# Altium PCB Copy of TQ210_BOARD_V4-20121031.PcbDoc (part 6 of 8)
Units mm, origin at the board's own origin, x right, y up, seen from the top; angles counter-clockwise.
Board outline 191.2 x 131.27 mm, 2 copper layers (TopLayer, BottomLayer); 362 components, 455 nets, 1594 pads, 630 vias.
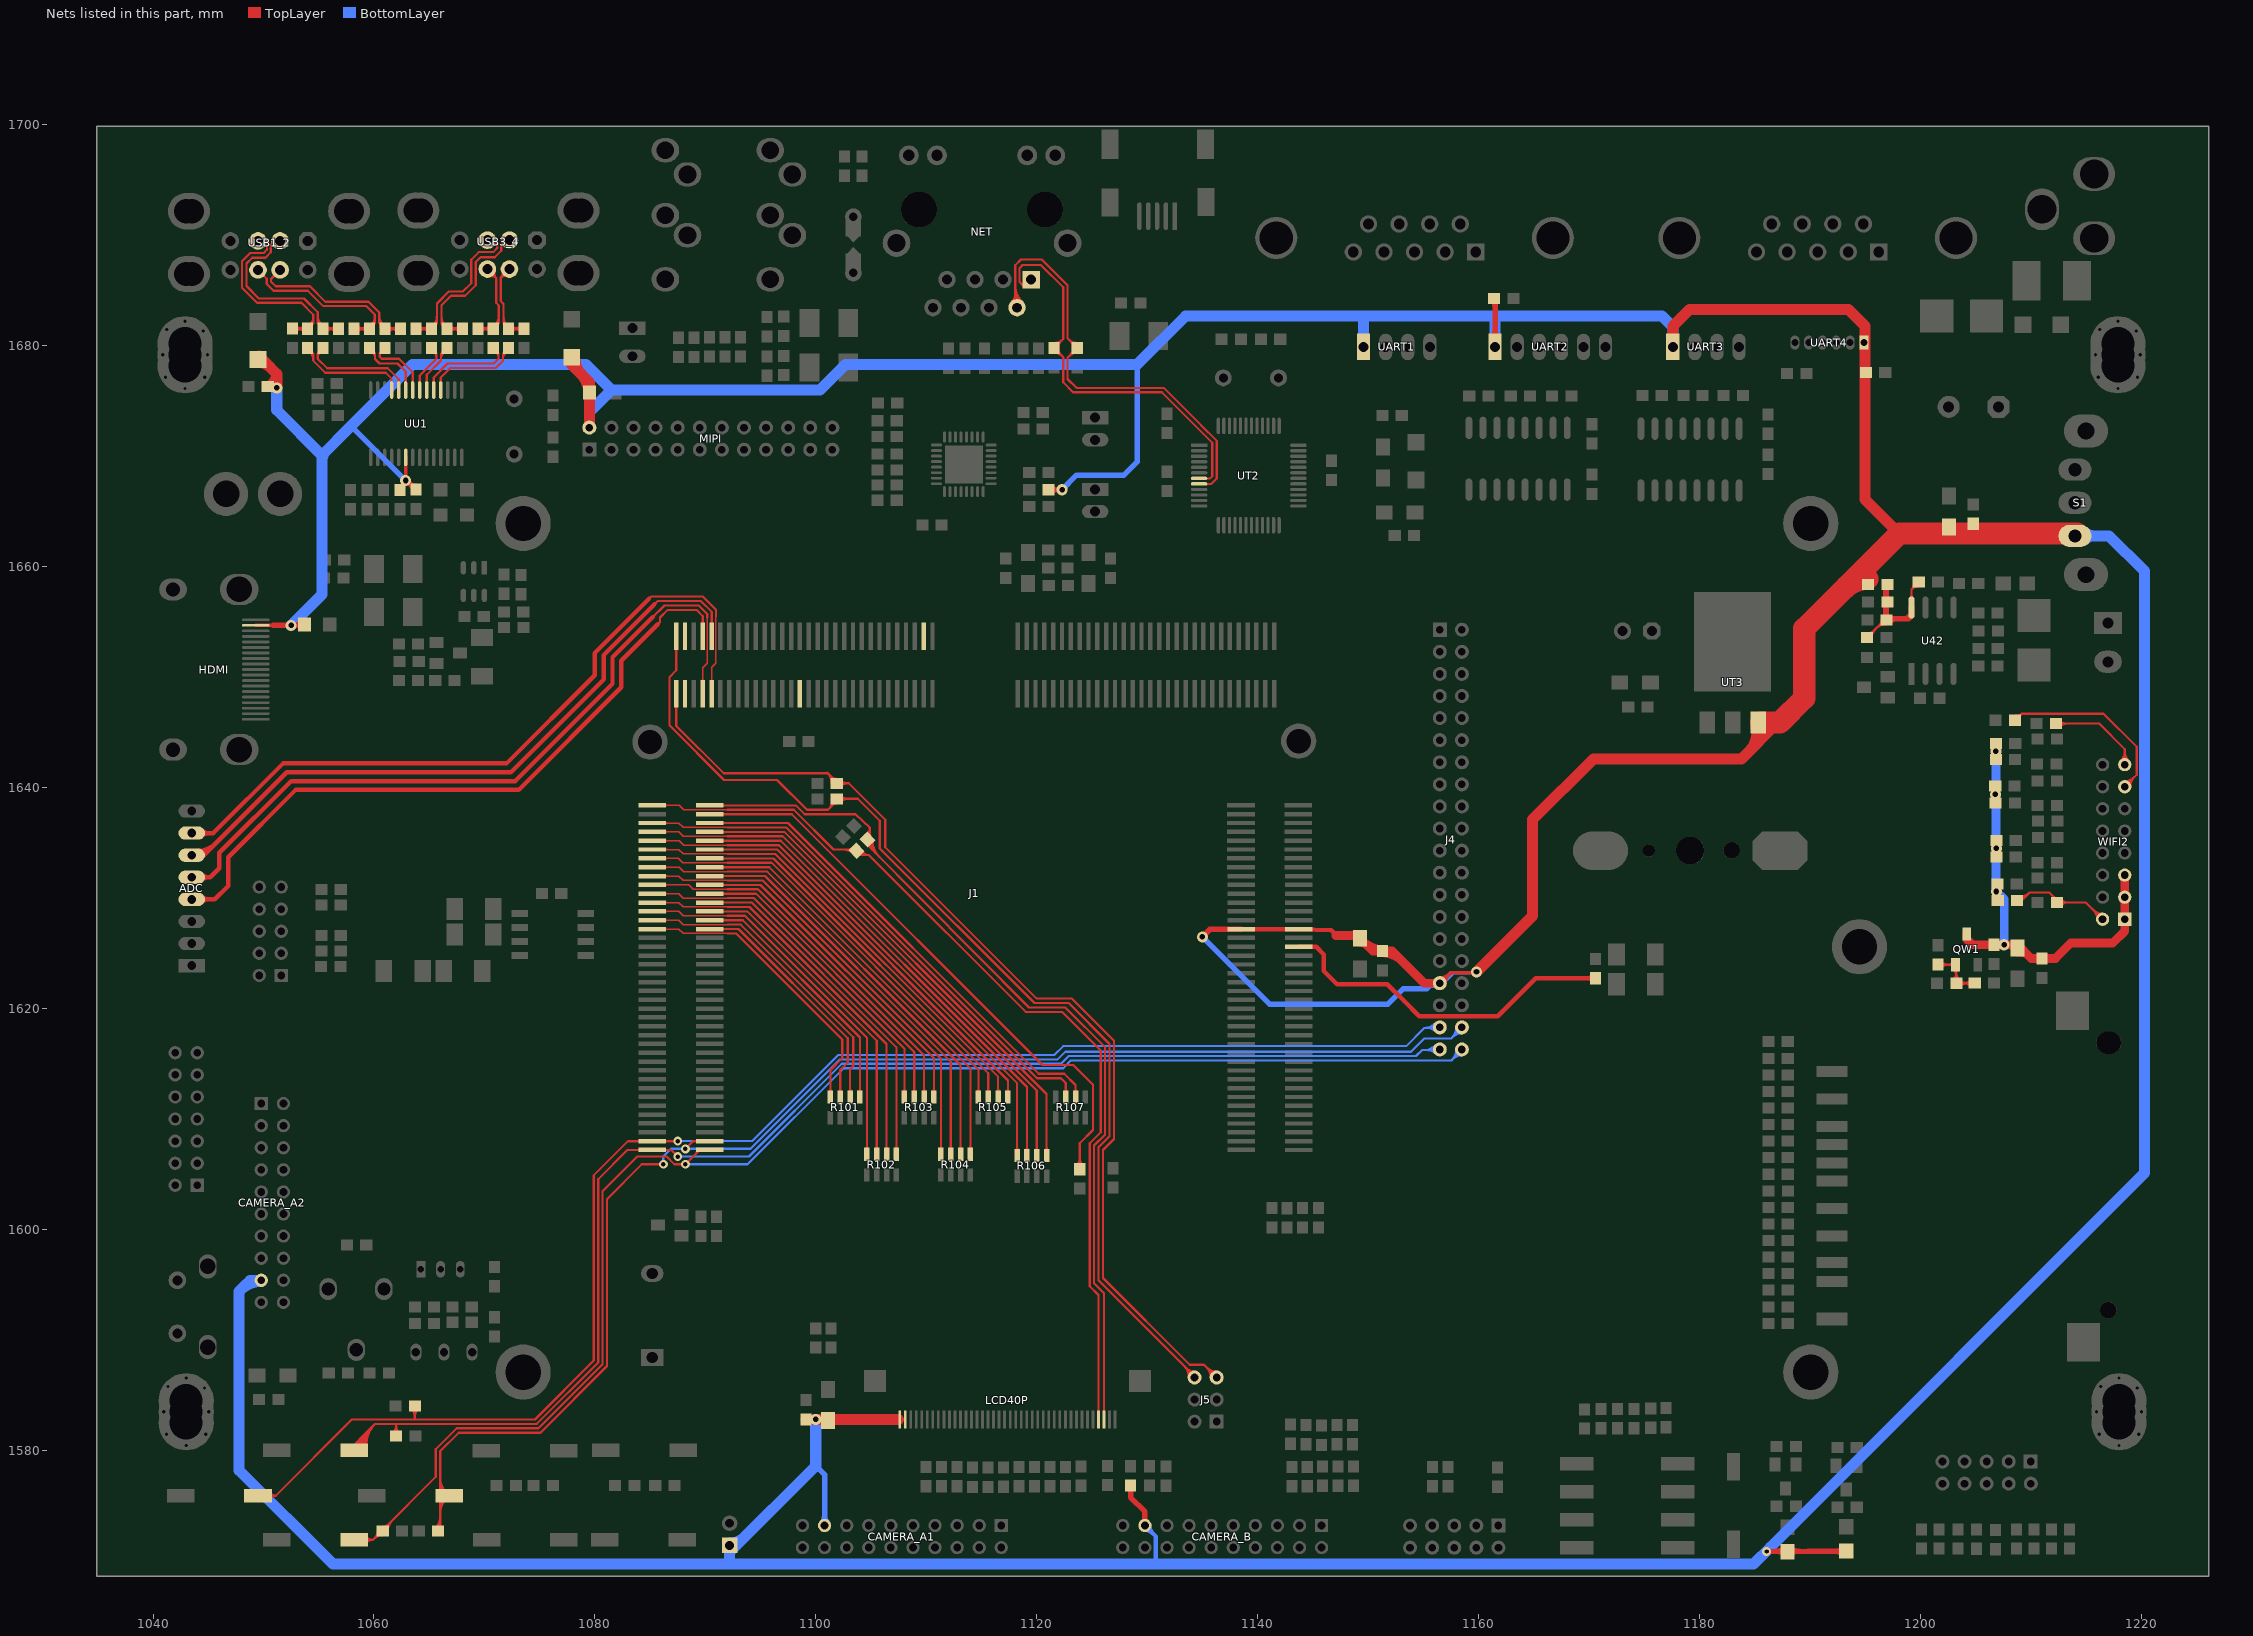
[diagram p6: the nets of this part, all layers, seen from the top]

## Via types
v1: diameter 1, hole 0.5, TopLayer to BottomLayer, 458 vias
v2: diameter 0.8, hole 0.4, TopLayer to BottomLayer, 172 vias

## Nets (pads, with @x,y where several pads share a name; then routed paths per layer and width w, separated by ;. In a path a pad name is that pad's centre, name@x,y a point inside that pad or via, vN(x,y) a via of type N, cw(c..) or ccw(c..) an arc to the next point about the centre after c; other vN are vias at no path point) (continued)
SD3_WPN: RW8.2 RW16.2 WIFI2.2 | length 17.4
  TopLayer w0.2: RW8.2@1208.765,1629.774 1209.174,1629.774 1209.9,1630.5 ; RW8.2@1208.815,1629.774 ccw(c1208.912,1630.38) 1209.346,1629.946 ; RW8.2@1208.846,1629.971 ccw(c1208.988,1630.858) 1209.623,1630.223 ; RW8.2@1208.878,1630.169 ccw(c1209.065,1631.335) 1209.9,1630.5 ; 1211.866,1630.339 cw(c1211.236,1629.71) RW16.2@1212.122,1629.624 ; RW16.2@1212.114,1630.091 ccw(c1212.321,1630.298) RW16.2@1212.321,1630.005 ; RW16.2@1212.371,1629.605 1214.995,1629.605 WIFI2.2@1216.512,1628.088 ; RW16.2@1212.6,1629.605 1211.705,1630.5 1209.9,1630.5 ; RW16.2@1212.704,1629.322 cw(c1213.387,1628.639) 1213.387,1629.605 cw(c1213.387,1630.571) RW16.2@1212.704,1629.888 ; WIFI2.2@1216.012,1628.088 ccw(c1214.805,1628.088) 1215.658,1628.942 ccw(c1216.512,1629.795) WIFI2.2@1216.512,1628.588 ; WIFI2.2@1216.212,1628.088 ccw(c1215.487,1628.088) 1215.999,1628.6 ccw(c1216.512,1629.112) WIFI2.2@1216.512,1628.388
SYS_OE: J1.84
TSXM0: ADC.6 J1.89 | length 63.1
  TopLayer w0.2: 1085.4,1656.6 1085.7,1656.9 1089.595,1656.9 1090.575,1655.92 J1.89@1090.575,1653.687
  TopLayer w0.4: ADC.6@1043.502,1633.888 1044.588,1633.888 1052.1,1641.4 1072.4,1641.4 1080.804,1649.804 1080.804,1652.004 1085.4,1656.6 ; ADC.6@1044.102,1633.888 ccw(c1044.102,1635.061) 1044.931,1634.231 ; ADC.6@1044.102,1634.288 ccw(c1044.102,1636.427) 1045.614,1634.914
TSXM1: CL1.1 J1.79 LCD40P.37 | length 89.3
  TopLayer w0.135: J1.79@1085.2,1638.4 1087.658,1638.4 1088.058,1638 1092,1638 ; J1.79@1086.344,1638.306 cw(c1086.57,1638.08) 1086.57,1638.4 cw(c1086.57,1638.72) J1.79@1086.344,1638.494
  TopLayer w0.2: 1092,1638 1098,1638 1101.603,1634.397 1103.603,1634.397 1104.1,1633.9 1104.8,1633.9 ; 1102.536,1634.397 cw(c1102.536,1633.21) CL1.1@1103.375,1634.049 ; 1102.848,1634.397 ccw(c1102.848,1635.142) CL1.1@1103.375,1634.615 ; CL1.1@1103.019,1634.397 cw(c1103.019,1633.693) CL1.1@1103.516,1634.191 ; CL1.1@1103.728,1634.261 ccw(c1104.237,1634.439) 1104.237,1633.9 ; CL1.1@1103.917,1634.327 ccw(c1104.518,1634.537) 1104.518,1633.9 ; CL1.1@1103.931,1633.917 cw(c1104.004,1633.794) 1104.105,1633.895 cw(c1104.21,1634) CL1.1@1104.08,1634.071 ; CL1.1@1104.106,1634.393 ccw(c1104.8,1634.635) 1104.8,1633.9 ; LCD40P.37@1125.6,1582.8 1125.6,1594.064 1124.8,1594.864 1124.8,1607.8 1125.8,1608.8 1125.8,1616.2 1122.3,1619.7 1119,1619.7 1104.8,1633.9
TSXP0: ADC.7 J1.90 | length 67.3
  TopLayer w0.135: J1.90@1090.565,1648.497 1090.565,1650.889 1090.965,1651.289 1090.965,1655.486
  TopLayer w0.2: 1084.9,1657.1 1085.1,1657.3 1089.795,1657.3 1090.955,1656.139 1090.955,1655.496
  TopLayer w0.4: ADC.7@1043.502,1635.888 1045.456,1635.888 1051.769,1642.2 1072,1642.2 1079.986,1650.186 1079.986,1652.186 1084.9,1657.1 ; ADC.7@1044.385,1635.605 cw(c1045.067,1634.922) 1045.067,1635.888 cw(c1045.067,1636.853) ADC.7@1044.385,1636.171
TSXP1: CL2.1 J1.80 LCD40P.38 | length 86.4
  TopLayer w0.2: J1.80@1090.409,1638.385 1090.424,1638.4 1098.2,1638.4 1099,1637.6 1103.6,1637.6 1104.9,1636.4 ; CL2.1@1104.47,1635.686 ccw(c1104.091,1636.4) 1104.9,1636.4 ; CL2.1@1104.564,1635.509 ccw(c1104.268,1636.068) 1104.9,1636.068 ; CL2.1@1104.658,1634.868 cw(c1104.606,1634.578) 1104.9,1634.578 ; CL2.1@1104.728,1635.261 ccw(c1105.903,1635.257) 1105.069,1634.429 ; 1104.9,1634.711 cw(c1105.279,1634.711) CL2.1@1105.011,1634.979 ; CL2.1@1104.928,1635.261 ccw(c1106.586,1635.255) 1105.41,1634.087 ; CL2.1@1105.128,1635.26 ccw(c1107.269,1635.253) 1105.75,1633.744 ; LCD40P.38@1126.1,1583 1126.1,1594.232 1125.2,1595.132 1125.2,1607.6 1126.2,1608.6 1126.2,1616.5 1122.6,1620.1 1119.3,1620.1 1104.9,1634.6 1104.9,1636.4
TSYM0: ADC.4 J1.87 | length 63.9
  TopLayer w0.2: 1085.7,1654.8 1085.9,1655 1085.9,1655.4 1086.6,1656.1 1089.195,1656.1 1089.775,1655.52 J1.87@1089.775,1653.687
  TopLayer w0.4: ADC.4@1043.502,1629.888 1045.588,1629.888 1046.8,1631.1 1046.8,1633.7 1052.9,1639.8 1073.1,1639.8 1082.4,1649.1 1082.4,1651.5 1085.7,1654.8 ; ADC.4@1044.385,1629.605 cw(c1045.067,1628.922) 1045.067,1629.888 cw(c1045.067,1630.853) ADC.4@1044.385,1630.171
TSYM1: CL3.1 J1.81 J5.6 | length 107.3
  TopLayer w0.2: J1.81@1087.294,1652.576 cw(c1087.098,1652.38) 1087.375,1652.38 ; 1087.375,1652.431 cw(c1087.581,1652.431) J1.81@1087.435,1652.576 ; J1.81@1087.375,1653.687 1087.375,1650.625 1086.75,1650 1086.75,1645.65 1091.7,1640.7 1096.5,1640.7 1099.2,1638 1101.1,1638 1102.1,1639 1103.8,1639 1105.8,1637 1105.8,1634.5 1119.8,1620.5 1122.9,1620.5 1126.6,1616.8 1126.6,1608.434 1125.6,1607.434 1125.6,1595.4 1134.3,1586.7 J5.6@1134.3,1586.6 ; 1101.223,1638.123 ccw(c1100.615,1638.731) CL3.1@1101.456,1638.91 ; 1101.483,1638.383 ccw(c1101.044,1638.822) CL3.1@1101.652,1638.951 ; 1101.583,1638.483 cw(c1101.847,1638.219) CL3.1@1101.847,1638.593 ; CL3.1@1102.089,1638.851 cw(c1102.448,1638.492) 1102.448,1639 ; CL3.1@1102.23,1638.71 cw(c1102.931,1638.009) 1102.931,1639 ; CL3.1@1102.23,1639.275 ccw(c1102.895,1639.94) 1102.895,1639 ; 1133.316,1587.684 cw(c1132.232,1586.6) 1133.765,1586.6 ccw(c1132.232,1586.6) 1133.316,1587.684 ; 1133.557,1587.443 ccw(c1134.3,1588.185) 1134.3,1587.135 cw(c1134.3,1588.185) 1133.557,1587.443 ; 1133.657,1587.343 cw(c1132.915,1586.6) 1133.965,1586.6 ccw(c1132.915,1586.6) 1133.657,1587.343 ; 1133.899,1587.101 ccw(c1134.3,1587.502) 1134.3,1586.935 cw(c1134.3,1587.502) 1133.899,1587.101
TSYP0: ADC.5 J1.88 | length 68.8
  TopLayer w0.135: J1.88@1089.671,1649.641 ccw(c1089.445,1649.867) 1089.765,1649.867 ccw(c1090.084,1649.867) J1.88@1089.858,1649.641 ; J1.88@1089.765,1648.497 1089.765,1650.876 1090.164,1651.276 1090.164,1655.391
  TopLayer w0.2: 1085.253,1655.453 1086.3,1656.5 1089.395,1656.5 1090.172,1655.722 1090.172,1655.399
  TopLayer w0.4: ADC.5@1043.502,1631.888 1045.188,1631.888 1046,1632.7 1046,1634.1 1052.5,1640.6 1072.8,1640.6 1081.6,1649.4 1081.6,1651.8 1085.253,1655.453 ; ADC.5@1044.385,1631.605 cw(c1045.067,1630.922) 1045.067,1631.888 cw(c1045.067,1632.853) ADC.5@1044.385,1632.171
TSYP1: CL4.1 J1.82 J5.5 | length 102.8
  TopLayer w0.2: J1.82@1087.294,1647.376 cw(c1087.098,1647.181) 1087.375,1647.181 ; 1087.375,1647.231 cw(c1087.581,1647.231) J1.82@1087.435,1647.376 ; J1.82@1087.375,1648.487 1087.375,1645.591 1091.666,1641.3 1101.1,1641.3 1102,1640.4 1103,1640.4 1106.3,1637.1 1106.3,1634.6 1120,1620.9 1123.2,1620.9 1127,1617.1 1127,1608.2 1126,1607.2 1126,1595.6 1133.852,1587.748 1135.152,1587.748 J5.5@1136.3,1586.6 ; 1101.051,1641.349 cw(c1100.095,1640.393) CL4.1@1101.447,1640.393 ; 1101.393,1641.007 cw(c1100.778,1640.393) CL4.1@1101.647,1640.393 ; 1101.438,1640.962 ccw(c1101.847,1641.372) CL4.1@1101.847,1640.793 ; CL4.1@1102.089,1640.251 cw(c1102.448,1639.892) 1102.448,1640.4 ; CL4.1@1102.23,1640.11 cw(c1102.931,1639.409) 1102.931,1640.4 ; CL4.1@1102.23,1640.675 ccw(c1102.895,1641.34) 1102.895,1640.4 ; 1135.387,1587.513 cw(c1134.473,1586.6) 1135.765,1586.6 ccw(c1134.473,1586.6) 1135.387,1587.513 ; 1135.387,1587.513 ccw(c1136.3,1588.427) 1136.3,1587.135 cw(c1136.3,1588.427) 1135.387,1587.513 ; 1135.728,1587.172 cw(c1135.156,1586.6) 1135.965,1586.6 ccw(c1135.156,1586.6) 1135.728,1587.172 ; 1135.728,1587.172 ccw(c1136.3,1587.744) 1136.3,1586.935 cw(c1136.3,1587.744) 1135.728,1587.172
TX+: NET.1 R206.1 UT2.7 | length 40.3
  TopLayer w0.2: NET.1@1119.073,1685.468 1118.768,1685.468 1118.457,1685.779 1118.457,1687.062 1118.718,1687.322 1120.378,1687.322 1122.4,1685.3 1122.4,1680.638 R206.1@1121.577,1679.815 1122.4,1678.992 1122.4,1676.7 1123.3,1675.8 1131.334,1675.8 1135.9,1671.234 1135.9,1668.2 1135.704,1668.004 UT2.7@1134.703,1668.004 ; R206.1@1121.577,1679.365 cw(c1121.577,1678.279) 1122.345,1679.047 ; R206.1@1121.577,1679.565 cw(c1121.577,1678.961) R206.1@1122.004,1679.388 ; R206.1@1121.577,1680.065 ccw(c1121.577,1680.669) R206.1@1122.004,1680.242 ; R206.1@1121.577,1680.265 ccw(c1121.577,1681.351) 1122.345,1680.583 ; R206.1@1121.977,1679.765 ccw(c1122.822,1679.765) 1122.225,1679.168 ; R206.1@1121.977,1679.865 cw(c1122.822,1679.865) 1122.225,1680.462
TX-: NET.2 R207.1 UT2.8 | length 51
  TopLayer w0.2: NET.2@1117.744,1683.946 ccw(c1116.988,1684.702) 1118.057,1684.702 ; 1118.057,1684.571 ccw(c1119.341,1684.571) NET.2@1118.433,1683.663 ; 1118.057,1685.054 ccw(c1119.824,1685.054) NET.2@1118.575,1683.805 ; 1118.057,1685.537 ccw(c1120.307,1685.537) NET.2@1118.716,1683.946 ; NET.2@1118.23,1683.46 1118.057,1683.633 1118.057,1687.297 1118.591,1687.83 1120.47,1687.83 1122.8,1685.5 1122.8,1680.692 R207.1@1123.677,1679.815 1122.8,1678.938 1122.8,1677 1123.6,1676.2 1131.5,1676.2 1136.3,1671.4 ; 1122.909,1679.047 cw(c1123.677,1678.279) R207.1@1123.677,1679.365 ; 1122.909,1680.583 ccw(c1123.677,1681.351) R207.1@1123.677,1680.265 ; 1123.03,1679.168 ccw(c1122.432,1679.765) R207.1@1123.277,1679.765 ; 1123.03,1680.462 cw(c1122.432,1679.865) R207.1@1123.277,1679.865 ; R207.1@1123.25,1679.388 cw(c1123.677,1678.961) R207.1@1123.677,1679.565 ; R207.1@1123.25,1680.242 ccw(c1123.677,1680.669) R207.1@1123.677,1680.065 ; UT2.8@1134.703,1667.504 1135.804,1667.504 1136.3,1668 1136.3,1671.4 ; 1134.9,1672.8 1136.3,1671.4
USB1-DM: RU1.1 UU1.10 | length 12
  TopLayer w0.2: 1054.9,1678.902 1054.913,1678.915 ; 1054.913,1678.937 cw(c1055.538,1678.937) RU1.1@1055.433,1679.553 ; 1054.913,1679.173 cw(c1055.498,1679.173) RU1.1@1055.4,1679.75 ; RU1.1@1055.4,1679.8 1054.913,1679.313 1054.913,1678.82 1055.764,1677.968 1061.244,1677.968 1062.235,1676.977 UU1.10@1062.235,1676
USB1-DP: RU2.1 UU1.11 | length 12
  TopLayer w0.2: RU2.1@1053.945,1679.558 cw(c1053.735,1678.822) 1054.5,1678.822 ; RU2.1@1054,1679.75 cw(c1053.811,1679.087) 1054.5,1679.087 ; RU2.1@1054,1679.8 1054.5,1679.3 1054.5,1678.667 1055.599,1677.568 1061.06,1677.568 1061.6,1677.028 UU1.11@1061.6,1676
USB1_D+: RU2.2 RU4.2 USB1_2.3 | length 23
  TopLayer w0.2: USB1_2.3@1049.5,1689.5 1049.906,1689.5 1050.305,1689.102 1050.305,1688.695 1050.025,1688.416 1048.806,1688.416 1048.044,1687.654 1048.044,1685.266 1049.41,1683.9 1053.433,1683.9 1054.506,1682.826 1054.506,1682.056 ; RU4.2@1052.62,1681.565 1052.635,1681.55 RU2.2@1054,1681.55 1054.506,1682.056 ; RU4.2@1052.761,1681.707 ccw(c1053.14,1682.085) 1053.14,1681.55 ; RU4.2@1052.903,1681.283 cw(c1053.548,1680.637) RU2.2@1053.548,1681.55 ; RU4.2@1052.903,1681.848 ccw(c1053.623,1682.568) RU2.2@1053.623,1681.55 ; RU2.2@1053.717,1681.267 ccw(c1053.034,1680.584) 1053.034,1681.55 ccw(c1053.034,1682.516) RU2.2@1053.717,1681.833 ; RU2.2@1053.941,1681.791 ccw(c1053.707,1682.556) 1054.506,1682.556 ; RU2.2@1054,1681.6 ccw(c1053.79,1682.285) 1054.506,1682.285 ; RU2.2@1054.138,1681.975 ccw(c1054.259,1682.304) 1054.506,1682.056 ; RU2.2@1054.392,1681.679 cw(c1054.802,1681.761) 1054.506,1682.056
USB1_D-: RU1.2 RU3.2 USB1_2.2 | length 22
  TopLayer w0.2: USB1_2.2@1051.5,1689.5 1051.033,1689.5 1050.66,1689.127 1050.66,1688.467 1050.178,1687.984 1048.984,1687.984 1048.45,1687.451 1048.45,1685.425 1049.576,1684.3 1053.668,1684.3 1054.913,1683.055 1054.913,1682.037 RU1.2@1055.4,1681.55 RU3.2@1056.8,1681.55 ; 1054.913,1682.399 ccw(c1055.811,1682.399) RU1.2@1055.4,1681.6 ; 1054.913,1682.727 ccw(c1055.98,1682.727) RU1.2@1055.492,1681.778 ; RU1.2@1055.683,1681.267 cw(c1056.366,1680.584) 1056.366,1681.55 cw(c1056.366,1682.516) RU1.2@1055.683,1681.833 ; RU3.2@1056.517,1681.267 ccw(c1055.834,1680.584) 1055.834,1681.55 ccw(c1055.834,1682.516) RU3.2@1056.517,1681.833
USB2-DM: RU5.1 UU1.8 | length 6.1
  TopLayer w0.2: RU5.1@1061,1679.8 1060.526,1679.326 1060.526,1679.016 1060.704,1678.838 1062.27,1678.838 1063.505,1677.603 UU1.8@1063.505,1676
USB2-DP: RU6.1 UU1.9 | length 7.8
  TopLayer w0.2: RU6.1@1059.566,1679.553 cw(c1059.46,1678.927) 1060.094,1678.927 ; RU6.1@1059.6,1679.75 cw(c1059.5,1679.164) 1060.094,1679.164 ; RU6.1@1059.6,1679.8 1060.094,1679.306 1060.094,1678.813 1060.501,1678.407 1062.136,1678.407 1062.87,1677.673 UU1.9@1062.87,1676
USB2_D+: RU6.2 RU8.2 USB1_2.7 | length 20.3
  TopLayer w0.2: USB1_2.7@1049.5,1686.88 1050.3,1686.08 1050.3,1685.6 1050.9,1685 1054,1685 1055.4,1683.6 1059.321,1683.6 1060.069,1682.852 1060.069,1682.019 RU6.2@1059.6,1681.55 RU8.2@1058.2,1681.55 ; RU8.2@1058.483,1681.267 cw(c1059.166,1680.584) 1059.166,1681.55 cw(c1059.166,1682.516) RU8.2@1058.483,1681.833 ; RU6.2@1059.317,1681.267 ccw(c1058.634,1680.584) 1058.634,1681.55 ccw(c1058.634,1682.516) RU6.2@1059.317,1681.833 ; RU6.2@1059.53,1681.787 ccw(c1059.241,1682.564) 1060.069,1682.564 ; RU6.2@1059.6,1681.6 ccw(c1059.348,1682.275) 1060.069,1682.275
USB2_D-: RU5.2 RU7.2 USB1_2.6 | length 21.5
  TopLayer w0.2: USB1_2.6@1051.5,1686.88 1050.686,1686.066 1050.686,1685.814 1051.1,1685.4 1054.2,1685.4 1055.6,1684 1059.505,1684 1060.475,1683.029 1060.475,1682.075 RU5.2@1061,1681.55 RU7.2@1062.4,1681.55 ; 1060.475,1682.411 ccw(c1061.365,1682.411) RU5.2@1061,1681.6 ; 1060.475,1682.72 ccw(c1061.504,1682.72) RU5.2@1061.082,1681.782 ; RU5.2@1060.609,1681.683 ccw(c1060.218,1681.767) 1060.5,1682.05 ccw(c1060.737,1682.286) RU5.2@1060.857,1681.974 ; RU5.2@1061.283,1681.267 cw(c1061.966,1680.584) 1061.966,1681.55 cw(c1061.966,1682.516) RU5.2@1061.283,1681.833 ; RU7.2@1062.117,1681.267 ccw(c1061.434,1680.584) 1061.434,1681.55 ccw(c1061.434,1682.516) RU7.2@1062.117,1681.833
USB3-DM: RU9.1 UU1.6 | length 6.5
  TopLayer w0.2: UU1.6@1064.775,1676 1064.775,1677.381 1066.063,1678.669 1066.063,1679.263 RU9.1@1066.6,1679.8 ; 1066.063,1678.801 cw(c1066.843,1678.801) RU9.1@1066.65,1679.556 ; 1066.063,1679.059 cw(c1066.777,1679.059) RU9.1@1066.6,1679.75
USB3-DP: RU10.1 UU1.7 | length 6.2
  TopLayer w0.2: UU1.7@1064.14,1676 1064.14,1677.311 1065.657,1678.828 1065.657,1679.343 RU10.1@1065.2,1679.8 ; RU10.1@1065.164,1679.553 cw(c1065.055,1678.961) 1065.657,1678.961 ; RU10.1@1065.2,1679.75 cw(c1065.099,1679.201) 1065.657,1679.201
USB3_D+: RU10.2 RU12.2 USB3_4.3 | length 21.3
  TopLayer w0.2: RU12.2@1063.8,1681.55 RU10.2@1065.2,1681.55 1065.708,1682.058 ; RU12.2@1064.083,1681.267 cw(c1064.766,1680.584) 1064.766,1681.55 cw(c1064.766,1682.516) RU12.2@1064.083,1681.833 ; RU10.2@1064.917,1681.267 ccw(c1064.234,1680.584) 1064.234,1681.55 ccw(c1064.234,1682.516) RU10.2@1064.917,1681.833 ; RU10.2@1065.2,1681.6 ccw(c1063.974,1682.826) 1065.708,1682.826 ; RU10.2@1065.337,1681.976 ccw(c1065.458,1682.307) 1065.708,1682.058 ; RU10.2@1065.341,1681.459 ccw(c1064.457,1682.343) 1065.708,1682.343 ; RU10.2@1065.592,1681.678 cw(c1066.006,1681.76) 1065.708,1682.058 ; USB3_4.3@1070.266,1689.576 1070.769,1689.576 1071.169,1689.176 1071.169,1688.871 1070.788,1688.49 1069.492,1688.49 1068.807,1687.805 1068.807,1685.671 1068.07,1684.934 1066.8,1684.934 1065.708,1683.842 1065.708,1682.058 ; USB3_4.3@1070.435,1689.328 cw(c1070.72,1688.909) 1071.078,1689.267 ; USB3_4.3@1070.966,1689.576 ccw(c1071.443,1689.576) 1071.106,1689.239
USB3_D-: RU9.2 RU11.2 USB3_4.2 | length 19.1
  TopLayer w0.2: 1066.114,1682.272 ccw(c1067.247,1682.272) RU9.2@1066.461,1681.456 ; 1066.114,1682.742 ccw(c1067.7,1682.742) RU9.2@1066.6,1681.6 ; RU9.2@1066.883,1681.267 cw(c1067.566,1680.584) 1067.566,1681.55 cw(c1067.566,1682.516) RU9.2@1066.883,1681.833 ; RU11.2@1067.717,1681.267 ccw(c1067.034,1680.584) 1067.034,1681.55 ccw(c1067.034,1682.516) RU11.2@1067.717,1681.833 ; RU11.2@1068,1681.55 RU9.2@1066.6,1681.55 1066.114,1682.036 1066.114,1683.683 1066.966,1684.534 1068.254,1684.534 1069.213,1685.493 1069.213,1687.601 1069.645,1688.033 1070.94,1688.033 1071.524,1688.617 1071.524,1689.176 1071.924,1689.576 USB3_4.2@1072.266,1689.576
USB4-DM: RU13.1 UU1.4 | length 10.7
  TopLayer w0.2: UU1.4@1066.045,1676 1066.045,1677.144 1066.902,1678 1071.016,1678 1071.677,1678.661 1071.677,1679.277 RU13.1@1072.2,1679.8 ; 1071.677,1678.803 cw(c1072.458,1678.803) RU13.1@1072.253,1679.557 ; 1071.677,1679.065 cw(c1072.387,1679.065) RU13.1@1072.2,1679.75
USB4-DP: RU14.1 UU1.5 | length 10.5
  TopLayer w0.2: UU1.5@1065.41,1676 1065.41,1677.144 1066.667,1678.4 1070.832,1678.4 1071.27,1678.838 1071.27,1679.33 RU14.1@1070.8,1679.8 ; RU14.1@1070.767,1679.553 cw(c1070.67,1678.96) 1071.27,1678.96 ; RU14.1@1070.8,1679.75 cw(c1070.709,1679.196) 1071.27,1679.196
USB4_D+: RU14.2 RU16.2 USB3_4.7 | length 14.8
  TopLayer w0.2: RU16.2@1069.4,1681.55 RU14.2@1070.8,1681.55 1071.296,1682.046 1071.296,1683.664 1071.067,1683.893 1071.067,1686.155 ; RU16.2@1069.683,1681.267 cw(c1070.366,1680.584) 1070.366,1681.55 cw(c1070.366,1682.516) RU16.2@1069.683,1681.833 ; USB3_4.7@1070.266,1686.956 1071.067,1686.155 ; USB3_4.7@1070.425,1686.482 cw(c1070.552,1686.098) 1070.838,1686.384 cw(c1071.124,1686.67) USB3_4.7@1070.741,1686.798 ; USB3_4.7@1070.488,1686.292 cw(c1070.667,1685.755) 1071.067,1686.155 ; RU14.2@1070.517,1681.267 ccw(c1069.834,1680.584) 1069.834,1681.55 ccw(c1069.834,1682.516) RU14.2@1070.517,1681.833 ; RU14.2@1070.8,1681.6 ccw(c1069.731,1682.743) 1071.296,1682.743 ; USB3_4.7@1070.93,1686.735 ccw(c1071.467,1686.556) 1071.067,1686.155 ; RU14.2@1070.937,1681.454 ccw(c1070.163,1682.282) 1071.296,1682.282
USB4_D-: RU13.2 RU15.2 USB3_4.6 | length 14.7
  TopLayer w0.2: USB3_4.6@1071.604,1686.729 cw(c1071.086,1686.551) 1071.474,1686.163 ; 1071.728,1682.258 ccw(c1072.858,1682.258) RU13.2@1072.059,1681.459 ; 1071.728,1682.74 ccw(c1073.34,1682.74) RU13.2@1072.2,1681.6 ; USB3_4.6@1071.794,1686.794 cw(c1071.423,1686.667) 1071.7,1686.39 cw(c1071.977,1686.113) USB3_4.6@1072.104,1686.483 ; USB3_4.6@1072.039,1686.294 ccw(c1071.861,1685.776) 1071.474,1686.163 ; USB3_4.6@1072.266,1686.956 1071.474,1686.163 ; RU13.2@1072.483,1681.267 cw(c1073.166,1680.584) 1073.166,1681.55 cw(c1073.166,1682.516) RU13.2@1072.483,1681.833 ; RU15.2@1073.317,1681.267 ccw(c1072.634,1680.584) 1072.634,1681.55 ccw(c1072.634,1682.516) RU15.2@1073.317,1681.833 ; RU15.2@1073.6,1681.55 RU13.2@1072.2,1681.55 1071.728,1682.022 1071.728,1683.798 1071.474,1684.052 1071.474,1686.163
VCC_WIFI: CW2.2 CW5.1 QW1.3 RW1.1 RW2.1 RW3.1 RW4.1 RW5.1 RW6.1 RW7.1 RW8.1 RW21.1 WIFI2.1 WIFI2.3 WIFI2.5 | length 63.5
  TopLayer w0.5: QW1.3@1204.356,1626.536 ccw(c1205.178,1626.486) 1204.596,1625.904 ; RW21.1@1206.518,1625.602 ccw(c1206.091,1625.175) 1206.091,1625.779 ccw(c1206.091,1626.382) RW21.1@1206.518,1625.955 ; RW7.1@1206.595,1638.782 ccw(c1206.115,1639.261) v1@1206.793,1639.261 ; RW4.1@1206.616,1639.992 cw(c1206.19,1639.565) 1206.793,1639.565 cw(c1207.397,1639.565) RW4.1@1206.97,1639.992 ; RW5.1@1206.666,1642.746 ccw(c1206.223,1643.189) v1@1206.85,1643.189 ; RW6.1@1206.673,1643.823 cw(c1206.246,1643.396) 1206.85,1643.396 cw(c1207.454,1643.396) RW6.1@1207.027,1643.823 ; RW2.1@1206.716,1633.896 ccw(c1206.29,1634.323) 1206.893,1634.323 ccw(c1207.497,1634.323) RW2.1@1207.07,1633.896 ; RW3.1@1206.716,1635.042 cw(c1206.29,1634.615) 1206.893,1634.615 cw(c1207.497,1634.615) RW3.1@1207.07,1635.042 ; v1@1206.793,1639.156 ccw(c1207.323,1639.156) RW7.1@1206.948,1638.782 ; v1@1206.85,1643.156 ccw(c1207.43,1643.156) RW5.1@1207.02,1642.746 ; RW21.1@1206.872,1625.602 cw(c1207.299,1625.175) 1207.299,1625.779 cw(c1207.299,1626.382) RW21.1@1206.872,1625.955 ; v1@1207.483,1625.779 cw(c1207.483,1624.315) CW5.1@1208.518,1625.35 ; CW5.1@1208.79,1624.983 cw(c1208.79,1622.986) 1210.202,1624.398 ; CW2.2@1210.828,1624.358 ccw(c1210.401,1623.931) 1210.401,1624.535 ccw(c1210.401,1625.138) CW2.2@1210.828,1624.711 ; CW2.2@1211.182,1624.358 cw(c1211.609,1623.931) 1211.609,1624.535 cw(c1211.609,1625.138) CW2.2@1211.182,1624.711 ; WIFI2.1@1218.264,1627.841 cw(c1217.667,1627.243) 1218.512,1627.243 cw(c1219.357,1627.243) WIFI2.1@1218.759,1627.841 ; WIFI2.1@1218.264,1628.335 ccw(c1217.667,1628.933) 1218.512,1628.933 ccw(c1219.357,1628.933) WIFI2.1@1218.759,1628.335 ; WIFI2.3@1218.264,1629.841 cw(c1217.667,1629.243) 1218.512,1629.243 cw(c1219.357,1629.243) WIFI2.3@1218.759,1629.841 ; WIFI2.3@1218.264,1630.335 ccw(c1217.667,1630.933) 1218.512,1630.933 ccw(c1219.357,1630.933) WIFI2.3@1218.759,1630.335 ; WIFI2.5@1218.264,1631.841 cw(c1217.667,1631.243) 1218.512,1631.243 cw(c1219.357,1631.243) WIFI2.5@1218.759,1631.841
  TopLayer w0.8: QW1.3@1204.206,1626.745 1204.206,1626.294 1204.721,1625.779 1208.821,1625.779 1210.065,1624.535 1212.235,1624.535 1213.635,1625.935 1217.435,1625.935 1218.512,1627.012 WIFI2.5@1218.512,1632.088 ; RW4.1@1206.793,1640.169 1206.793,1638.633 RW7.1@1206.821,1638.605 ; RW5.1@1206.843,1642.569 1206.85,1642.576 RW6.1@1206.85,1644 ; RW2.1@1206.893,1633.719 RW3.1@1206.893,1635.219
  BottomLayer w0.8: v1@1206.85,1630.6 v1@1206.85,1643.309 ; v1(1206.892,1630.6) 1207.6,1629.892 v1(1207.6,1625.779)
  other v1: 1206.893,1634.5 1206.793,1639.4 1206.85,1643.3
VCLK: J1.78 R108.2 | length 54.3
  TopLayer w0.2: J1.78@1090.398,1637.595 1097.838,1637.595 ; 1097.838,1637.585 1120.526,1614.897 1123.303,1614.897 1125.1,1613.1 1125.1,1609 1123.9,1607.8 R108.2@1123.9,1605.65 ; R108.2@1123.617,1605.783 ccw(c1122.934,1606.466) 1123.9,1606.466 ccw(c1124.866,1606.466) R108.2@1124.183,1605.783
VD0: J1.51 R101.4 | length 27.5
  TopLayer w0.135: J1.51@1085.2,1627.2 1087.6,1627.2 1088,1626.8 1092,1626.8
  TopLayer w0.2: 1092,1626.8 1092.8,1626.8 1102.39,1617.21 1102.39,1615.5 1101.333,1614.443 R101.4@1101.333,1612 ; R101.4@1101.227,1612.456 ccw(c1100.971,1612.712) 1101.333,1612.712 ccw(c1101.695,1612.712) R101.4@1101.439,1612.456
VD1: J1.52 R101.3 | length 22.7
  TopLayer w0.2: J1.52@1090.4,1627.2 1093,1627.2 1102.89,1617.31 1102.89,1615.1 1102.222,1614.432 R101.3@1102.222,1612 ; R101.3@1102.116,1612.456 ccw(c1101.86,1612.712) 1102.222,1612.712 ccw(c1102.584,1612.712) R101.3@1102.328,1612.456
VD2: J1.53 R101.2 | length 29.2
  TopLayer w0.135: J1.53@1085.2,1628 1085.7,1628 1087.6,1628 1088,1627.6 1092,1627.6 ; J1.53@1086.344,1627.906 cw(c1086.57,1627.68) 1086.57,1628 cw(c1086.57,1628.32) J1.53@1086.344,1628.094
  TopLayer w0.2: 1092,1627.6 1093.2,1627.6 1103.4,1617.4 1103.4,1614.8 1103.111,1614.511 R101.2@1103.111,1612 ; R101.2@1103.005,1612.456 ccw(c1102.749,1612.712) 1103.111,1612.712 ccw(c1103.473,1612.712) R101.2@1103.217,1612.456
VD3: J1.54 R101.1 | length 24
  TopLayer w0.2: J1.54@1090.4,1628 1093.39,1628 1104,1617.39 R101.1@1104,1612 ; R101.1@1103.894,1612.456 ccw(c1103.638,1612.712) 1104,1612.712 ccw(c1104.362,1612.712) R101.1@1104.106,1612.456
VD4: J1.55 R102.4 | length 35.8
  TopLayer w0.135: J1.55@1085.2,1628.8 1087.6,1628.8 1088,1628.4 1092,1628.4 ; J1.55@1086.344,1628.706 cw(c1086.57,1628.48) 1086.57,1628.8 cw(c1086.57,1629.12) J1.55@1086.344,1628.894
  TopLayer w0.2: 1092,1628.4 1093.6,1628.4 1104.633,1617.367 R102.4@1104.633,1606.8 ; R102.4@1104.527,1607.256 ccw(c1104.271,1607.512) 1104.633,1607.512 ccw(c1104.995,1607.512) R102.4@1104.739,1607.256
VD5: J1.56 R102.3 | length 30.8
  TopLayer w0.2: J1.56@1090.4,1628.8 1093.8,1628.8 1105.522,1617.078 R102.3@1105.522,1606.8 ; R102.3@1105.416,1607.256 ccw(c1105.16,1607.512) 1105.522,1607.512 ccw(c1105.884,1607.512) R102.3@1105.628,1607.256
VD6: J1.57 R102.2 | length 37.6
  TopLayer w0.135: J1.57@1085.2,1629.6 1087.6,1629.6 1088,1629.2 1092,1629.2 ; J1.57@1086.344,1629.506 cw(c1086.57,1629.28) 1086.57,1629.6 cw(c1086.57,1629.92) J1.57@1086.344,1629.694
  TopLayer w0.2: 1092,1629.2 1094,1629.2 1106.411,1616.789 R102.2@1106.411,1606.8 ; R102.2@1106.305,1607.256 ccw(c1106.049,1607.512) 1106.411,1607.512 ccw(c1106.773,1607.512) R102.2@1106.517,1607.256
VD7: J1.58 R102.1 | length 32.6
  TopLayer w0.2: J1.58@1090.4,1629.6 1094.2,1629.6 1107.3,1616.5 R102.1@1107.3,1606.8 ; R102.1@1107.194,1607.256 ccw(c1106.938,1607.512) 1107.3,1607.512 ccw(c1107.662,1607.512) R102.1@1107.406,1607.256
VD8: J1.59 R103.4 | length 34.1
  TopLayer w0.135: J1.59@1085.2,1630.4 1087.6,1630.4 1088,1630 1092,1630 ; J1.59@1086.344,1630.306 cw(c1086.57,1630.08) 1086.57,1630.4 cw(c1086.57,1630.72) J1.59@1086.344,1630.494
  TopLayer w0.2: 1092,1630 1094.4,1630 1108.033,1616.367 R103.4@1108.033,1612 ; R103.4@1107.927,1612.456 ccw(c1107.671,1612.712) 1108.033,1612.712 ccw(c1108.395,1612.712) R103.4@1108.139,1612.456
VD9: J1.60 R103.3 | length 29.1
  TopLayer w0.2: J1.60@1090.4,1630.4 1094.6,1630.4 1108.922,1616.078 R103.3@1108.922,1612 ; R103.3@1108.816,1612.456 ccw(c1108.56,1612.712) 1108.922,1612.712 ccw(c1109.284,1612.712) R103.3@1109.028,1612.456
VD10: J1.61 R103.2 | length 35.8
  TopLayer w0.135: J1.61@1085.2,1631.2 1088.511,1631.2 1088.911,1630.8 1092,1630.8 ; J1.61@1086.344,1631.106 cw(c1086.57,1630.88) 1086.57,1631.2 cw(c1086.57,1631.52) J1.61@1086.344,1631.294
  TopLayer w0.2: 1092,1630.8 1094.771,1630.8 1109.811,1615.76 R103.2@1109.811,1612 ; R103.2@1109.705,1612.456 ccw(c1109.449,1612.712) 1109.811,1612.712 ccw(c1110.173,1612.712) R103.2@1109.917,1612.456
VD11: J1.62 R103.1 | length 30.9
  TopLayer w0.2: J1.62@1090.398,1631.195 1095.005,1631.195 1110.7,1615.5 R103.1@1110.7,1612 ; R103.1@1110.594,1612.456 ccw(c1110.338,1612.712) 1110.7,1612.712 ccw(c1111.062,1612.712) R103.1@1110.806,1612.456
VD12: J1.63 R104.4 | length 42.7
  TopLayer w0.135: J1.63@1085.2,1632 1087.582,1632 1087.981,1631.601 1092,1631.601 ; J1.63@1086.344,1631.906 cw(c1086.57,1631.68) 1086.57,1632 cw(c1086.57,1632.32) J1.63@1086.344,1632.094
  TopLayer w0.2: 1092,1631.601 1095.199,1631.601 1111.333,1615.467 R104.4@1111.333,1606.8 ; R104.4@1111.227,1607.256 ccw(c1110.971,1607.512) 1111.333,1607.512 ccw(c1111.695,1607.512) R104.4@1111.439,1607.256
VD13: J1.64 R104.3 | length 37.7
  TopLayer w0.2: J1.64@1090.398,1631.995 1095.405,1631.995 1112.222,1615.178 R104.3@1112.222,1606.8 ; R104.3@1112.116,1607.256 ccw(c1111.86,1607.512) 1112.222,1607.512 ccw(c1112.584,1607.512) R104.3@1112.328,1607.256
VD14: J1.65 R104.2 | length 44.5
  TopLayer w0.135: J1.65@1085.2,1632.8 1087.657,1632.8 1088.058,1632.399 1091.999,1632.399 ; J1.65@1086.344,1632.706 cw(c1086.57,1632.48) 1086.57,1632.8 cw(c1086.57,1633.12) J1.65@1086.344,1632.894
  TopLayer w0.2: 1092,1632.4 1095.6,1632.4 1113.111,1614.889 R104.2@1113.111,1606.8 ; R104.2@1113.005,1607.256 ccw(c1112.749,1607.512) 1113.111,1607.512 ccw(c1113.473,1607.512) R104.2@1113.217,1607.256
VD15: J1.66 R104.1 | length 39.5
  TopLayer w0.2: J1.66@1090.398,1632.795 1090.6,1632.795 1090.605,1632.8 1095.8,1632.8 1114,1614.6 R104.1@1114,1606.8 ; R104.1@1113.894,1607.256 ccw(c1113.638,1607.512) 1114,1607.512 ccw(c1114.362,1607.512) R104.1@1114.106,1607.256
VD16: J1.67 R105.4 | length 41
  TopLayer w0.135: J1.67@1085.2,1633.6 1087.568,1633.6 1087.967,1633.201 1091.999,1633.201 ; J1.67@1086.344,1633.506 cw(c1086.57,1633.28) 1086.57,1633.6 cw(c1086.57,1633.92) J1.67@1086.344,1633.694
  TopLayer w0.2: 1092,1633.2 1095.971,1633.2 ; 1095.971,1633.195 1096.005,1633.195 1114.733,1614.467 R105.4@1114.733,1612 ; R105.4@1114.627,1612.456 ccw(c1114.371,1612.712) 1114.733,1612.712 ccw(c1115.095,1612.712) R105.4@1114.839,1612.456
VD17: J1.68 R105.3 | length 36
  TopLayer w0.2: J1.68@1090.398,1633.595 1096.171,1633.595 1115.622,1614.144 R105.3@1115.622,1612 ; R105.3@1115.516,1612.456 ccw(c1115.26,1612.712) 1115.622,1612.712 ccw(c1115.984,1612.712) R105.3@1115.728,1612.456
VD18: J1.69 R105.2 | length 42.7
  TopLayer w0.135: J1.69@1085.2,1634.4 1087.6,1634.4 1088,1634 1092,1634 ; J1.69@1086.344,1634.306 cw(c1086.57,1634.08) 1086.57,1634.4 cw(c1086.57,1634.72) J1.69@1086.344,1634.494
  TopLayer w0.2: 1092.005,1633.995 1096.336,1633.995 1116.511,1613.82 R105.2@1116.511,1612 ; R105.2@1116.405,1612.456 ccw(c1116.149,1612.712) 1116.511,1612.712 ccw(c1116.873,1612.712) R105.2@1116.617,1612.456
VD19: J1.70 R105.1 | length 37.7
  TopLayer w0.2: J1.70@1090.398,1634.395 1096.502,1634.395 1117.4,1613.497 R105.1@1117.4,1612 ; R105.1@1117.294,1612.456 ccw(c1117.038,1612.712) 1117.4,1612.712 ccw(c1117.762,1612.712) R105.1@1117.506,1612.456
VD20: J1.71 R106.4 | length 49.7
  TopLayer w0.135: J1.71@1085.2,1635.2 1087.636,1635.2 1088.037,1634.799 1092.001,1634.799 ; J1.71@1086.344,1635.106 cw(c1086.57,1634.88) 1086.57,1635.2 cw(c1086.57,1635.52) J1.71@1086.344,1635.294
  TopLayer w0.2: 1092.005,1634.795 1096.668,1634.795 1118.233,1613.23 R106.4@1118.233,1606.7 ; R106.4@1118.127,1607.156 ccw(c1117.871,1607.412) 1118.233,1607.412 ccw(c1118.595,1607.412) R106.4@1118.339,1607.156
VD21: J1.72 R106.3 | length 44.7
  TopLayer w0.2: J1.72@1090.398,1635.195 1096.833,1635.195 1119.122,1612.906 R106.3@1119.122,1606.7 ; R106.3@1119.016,1607.156 ccw(c1118.76,1607.412) 1119.122,1607.412 ccw(c1119.484,1607.412) R106.3@1119.228,1607.156
VD22: J1.73 R106.2 | length 51.5
  TopLayer w0.135: J1.73@1085.2,1636 1087.6,1636 1087.999,1635.601 1091.999,1635.601 ; J1.73@1086.344,1635.906 cw(c1086.57,1635.68) 1086.57,1636 cw(c1086.57,1636.32) J1.73@1086.344,1636.094
  TopLayer w0.2: 1092.005,1635.595 1096.999,1635.595 1120.011,1612.583 R106.2@1120.011,1606.7 ; R106.2@1119.905,1607.156 ccw(c1119.649,1607.412) 1120.011,1607.412 ccw(c1120.373,1607.412) R106.2@1120.117,1607.156
VD23: J1.74 R106.1 | length 46.5
  TopLayer w0.2: J1.74@1090.398,1635.995 1090.403,1636 1097.16,1636 1120.9,1612.26 R106.1@1120.9,1606.7 ; R106.1@1120.794,1607.156 ccw(c1120.538,1607.412) 1120.9,1607.412 ccw(c1121.262,1607.412) R106.1@1121.006,1607.156
VDD: C423.2 L421.2 L422.2 R421.1 R425.2 U42.8 | length 23
  TopLayer w0.2: R421.1@1195.18,1653.598 1196.87,1655.287 C423.2@1196.96,1655.287 ; R421.1@1195.23,1653.998 ccw(c1195.23,1654.843) 1195.828,1654.245 ; R421.1@1195.43,1653.598 cw(c1196.034,1653.598) R421.1@1195.607,1654.024 ; R421.1@1195.63,1653.598 cw(c1196.717,1653.598) 1195.948,1654.366 ; 1195.988,1654.406 cw(c1196.91,1653.484) C423.2@1196.91,1654.787 ; 1196.326,1654.743 ccw(c1195.882,1655.187) C423.2@1196.51,1655.187 ; 1196.33,1654.747 cw(c1196.91,1654.167) C423.2@1196.91,1654.987 ; U42.8@1199.085,1657.16 ccw(c1198.786,1657.458) 1199.209,1657.458 ccw(c1199.631,1657.458) U42.8@1199.332,1657.16 ; U42.8@1199.209,1656 1199.209,1657.941 R425.2@1199.87,1658.602 ; R425.2@1199.424,1658.543 cw(c1198.756,1658.444) 1199.234,1657.966 cw(c1199.804,1657.396) R425.2@1199.815,1658.202
  TopLayer w0.5: C423.2@1196.733,1655.364 ccw(c1196.33,1655.767) 1196.9,1655.767 ; 1196.9,1655.815 ccw(c1197.537,1655.815) C423.2@1197.087,1655.364 ; 1196.9,1657.6 cw(c1197.777,1657.6) L422.2@1197.157,1658.221 ; L422.2@1196.9,1658.4 1196.9,1655.347 1196.96,1655.287 1198.787,1655.287 ; C423.2@1197.187,1655.011 cw(c1197.855,1654.342) 1197.855,1655.287 ; 1198.428,1655.287 ccw(c1198.428,1656.367) U42.8@1199.191,1655.603 ; 1198.956,1655.456 cw(c1199.209,1655.204) U42.8@1199.209,1655.561 ; U42.8@1199.184,1655.592 cw(c1198.787,1655.698) 1198.787,1655.287 ; U42.8@1199.209,1656.311 1199.209,1655.709 1198.787,1655.287 ; 1196.9,1657.595 ccw(c1197.777,1657.595) 1197.157,1656.974 cw(c1197.777,1657.595) 1196.9,1657.595
VDD5V: C21.1 C22.1 C23.1 C105.1 C106.1 C107.1 CAMERA_A1.17 CAMERA_A2.17 CAMERA_B.17 CM2.1 CM4.1 CMB2.1 CU4.1 CU6.1 CU7.1 CV1.1 FUSE2.2 FUSE3.2 HDMI.18 J1.229 J1.230 J3.1 J4.33 L422.1 L506.2 LCD40P.1 LCD40P.2 LED1.1 LED2.1 MIPI.2 RU20.1 S1.2 UART1.1 UART2.1 UART3.1 UART4.1 UT3.3 UU1.20 | length 753.1
  TopLayer w0.2: RU20.1@1062.279,1667.221 v1(1062.87,1667.812) ; RU20.1@1062.365,1667.408 ccw(c1062.365,1667.652) RU20.1@1062.538,1667.48 ; RU20.1@1062.551,1667.083 cw(c1062.993,1667.26) v1@1062.656,1667.598 ; RU20.1@1062.736,1667.157 cw(c1063.299,1667.383) v1(1062.87,1667.812) ; J1.229@1143.715,1627.195 J1.229@1143.734,1627.175 ; v1@1159.75,1623.25 v1@1160,1623.5
  TopLayer w0.3: HDMI.18@1049.3,1654.7 1050.9,1654.7 ; v1(1062.87,1667.812) UU1.20@1062.87,1669.904
  TopLayer w0.35: J4.33@1156.5,1622.25 1157.5,1623.25 v1@1159.75,1623.25 ; J4.33@1156.5,1622.76 ccw(c1156.5,1623.991) 1157.371,1623.121 ; J4.33@1156.96,1622.3 cw(c1157.95,1622.3) 1157.25,1623
  TopLayer w0.4: J1.230@1138.515,1627.195 J1.229@1143.715,1627.195 ; J1.229@1143.734,1627.175 1146.683,1627.099 1147.058,1626.724
  TopLayer w0.5: 1050.9,1654.7 CU7.1@1053.8,1654.7 ; v1@1052.803,1654.7 ccw(c1052.803,1655.644) CU7.1@1053.471,1654.976 ; v1@1052.943,1654.7 cw(c1052.943,1653.954) CU7.1@1053.471,1654.481 ; v1@1062.933,1667.812 CU4.1@1063.626,1667.12 ; v1@1063.202,1667.544 ccw(c1063.798,1668.14) CU4.1@1063.798,1667.297 ; L506.2@1121.078,1666.976 v1@1122.376,1666.976 ; L506.2@1121.305,1666.799 cw(c1121.731,1666.372) 1121.731,1666.976 cw(c1121.731,1667.58) L506.2@1121.305,1667.153 ; CV1.1@1128.51,1576.81 1128.51,1575.74 1129.8,1574.45 CAMERA_B.17@1129.8,1573.2 ; v1(1135,1626.5) 1135.684,1627.184 J1.230@1138.525,1627.184 ; UART2.1@1161.26,1680.749 ccw(c1160.663,1681.347) 1161.508,1681.347 ccw(c1162.353,1681.347) UART2.1@1161.755,1680.749 ; C107.1@1161.283,1684.113 cw(c1160.742,1683.572) 1161.508,1683.572 ; C107.1@1161.5,1684.2 1161.508,1684.192 UART2.1@1161.508,1679.902 ; v2@1186.191,1570.841 LED2.1@1193.3,1570.89 ; 1186.959,1570.847 ccw(c1186.952,1571.922) LED1.1@1187.717,1571.167 ; 1187.165,1570.848 cw(c1187.171,1570.064) LED1.1@1187.721,1570.622 ; LED1.1@1188.262,1571.171 ccw(c1189.017,1571.936) 1189.024,1570.861 ; LED1.1@1188.266,1570.626 cw(c1188.823,1570.076) 1188.818,1570.859 ; 1192.213,1570.883 cw(c1192.221,1569.731) LED2.1@1193.03,1570.551 ; 1192.527,1570.885 ccw(c1192.522,1571.592) LED2.1@1193.026,1571.095
  TopLayer w0.8: 1147.115,1626.616 1149.045,1626.616 1150.461,1625.2 1152.2,1625.2 1155.1,1622.3 J4.33@1156.5,1622.3 ; 1148.413,1626.616 cw(c1148.413,1625.649) C21.1@1149.097,1626.333 ; C21.1@1149.263,1626.01 cw(c1149.263,1625.073) 1149.926,1625.735 ; C21.1@1149.612,1626.049 ccw(c1151.3,1627.737) CMB2.1@1151.3,1625.35 ; CMB2.1@1151.3,1625.05 cw(c1151.3,1622.515) 1153.092,1624.308 ; CMB2.1@1151.33,1625.055 cw(c1151.731,1623.781) 1152.675,1624.725
  TopLayer w1: FUSE2.2@1049.5,1678.509 cw(c1049.5,1676.911) 1050.63,1678.041 ; FUSE2.2@1049.6,1679.071 1051.2,1677.471 ; C105.1@1050.44,1676.31 ccw(c1049.933,1677.471) 1051.2,1677.471 ; v1(1051.2,1676.2) 1051.2,1677.471 ; FUSE3.2@1077.9,1678.3 1079.5,1676.7 MIPI.2@1079.5,1672.6 ; FUSE3.2@1078.172,1678.976 ccw(c1080.461,1678.976) 1078.842,1677.358 ; 1078.754,1677.446 cw(c1077.14,1675.832) CU6.1@1079.422,1675.832 ; 1079.077,1677.123 cw(c1078.139,1676.184) CU6.1@1079.425,1675.857 ; CM4.1@1099.1,1582.8 v1(1100,1582.8) 1101.115,1582.801 LCD40P.1@1107.498,1582.802 ; v1(1159.824,1623.324) 1164.9,1628.4 1164.9,1637.1 1170.4,1642.6 1183.8,1642.6 1187.1,1645.9 ; UART3.1@1177.6,1679.9 1177.6,1681.8 1179.1,1683.3 1193.5,1683.3 1195,1681.8 1195,1666.1 1197.901,1663.199 ; 1184.539,1643.339 ccw(c1182.923,1644.955) UT3.3@1185.13,1645.548
  TopLayer w2: UT3.3@1185.6,1645.9 1187.3,1645.9 1189.5,1648.1 1189.5,1654.4 1198.1,1663 S1.2@1214.2,1663 ; 1193.126,1658.026 cw(c1195.23,1655.922) 1195.23,1658.898
  BottomLayer w0.2: J4.33@1156.5,1622.25 J4.33@1156.75,1622.25
  BottomLayer w0.35: J4.33@1156.75,1622.25 1157.75,1623.25 v1@1160,1623.25
  BottomLayer w0.4: CAMERA_B.17@1129.8,1572.8 cw(c1129.8,1571.834) 1130.483,1572.517 cw(c1131.166,1573.2) CAMERA_B.17@1130.2,1573.2 ; CAMERA_B.17@1129.8,1573.2 1130.8,1572.2 1130.8,1569.7
  BottomLayer w0.5: 1057.9,1672.782 1057.941,1672.741 v1(1062.87,1667.812) ; 1100,1578.6 1100.8,1577.8 CAMERA_A1.17@1100.8,1573.2 ; CAMERA_A1.17@1100.553,1573.447 ccw(c1099.955,1574.045) 1100.8,1574.045 ccw(c1101.645,1574.045) CAMERA_A1.17@1101.047,1573.447 ; v1(1122.3,1666.976) 1123.624,1668.3 1127.9,1668.3 1129.1,1669.5 1129.1,1678.3 ; v1(1135,1626.5) 1141.1,1620.4 1151.8,1620.4 1153.2,1621.8 1155.3,1621.8 1155.8,1622.3 ; 1155.45,1621.95 cw(c1155.883,1621.517) J4.33@1156.262,1621.998 ; 1155.632,1622.132 cw(c1156.347,1621.417) J4.33@1156.52,1622.413 ; 1155.848,1622.348 cw(c1156.233,1621.962) J4.33@1156.571,1622.39 ; J4.33@1156.175,1622.094 ccw(c1155.8,1621.856) 1155.8,1622.3 ; J4.33@1156.175,1622.506 cw(c1155.8,1622.744) 1155.8,1622.3 ; J4.33@1156.5,1622.3 1155.8,1622.3
  BottomLayer w1: 1047.922,1594.522 cw(c1049.8,1592.644) CAMERA_A2.17@1049.8,1595.3 ; 1048.3,1594.9 cw(c1049.391,1593.809) CAMERA_A2.17@1049.775,1595.303 ; CAMERA_A2.17@1049.8,1595.4 1048.8,1595.4 1047.8,1594.4 1047.8,1578.2 1056.3,1569.7 1184.9,1569.7 1186.465,1571.265 1220.3,1605.1 1220.3,1659.6 1217.104,1662.796 S1.2@1214.008,1662.796 ; v1(1051.2,1676.2) 1051.2,1674.2 1055.4,1670 ; v1(1052.5,1654.7) 1055.3,1657.5 1055.3,1670.1 1057.941,1672.741 1063.5,1678.3 1079.2,1678.3 1081.5,1676 ; MIPI.2@1079.5,1672.6 1079.5,1674 1081.5,1676 ; 1092.2,1569.7 J3.1@1092.2,1570.9 ; J3.1@1092.2,1571.6 ccw(c1092.2,1573.531) 1093.566,1572.166 ; J3.1@1092.3,1570.9 1100,1578.6 v1(1100,1582.8) ; UART1.1@1149.6,1679.9 1149.6,1682.6 ; UART2.1@1161.508,1679.902 1161.508,1682.492 ; UART3.1@1177.6,1680.1 1177.6,1681.7 1176.6,1682.7 1133.5,1682.7 1129.1,1678.3 1102.7,1678.3 1100.4,1676 1081.5,1676 ; S1.2@1214.861,1662.442 cw(c1215.715,1661.589) 1215.715,1662.796 cw(c1215.715,1664.003) S1.2@1214.861,1663.149
  other v2: 1186.091,1570.841
VDD_BATT: J1.233 R71.2 | length 34.8
  TopLayer w0.2: J1.233@1143.715,1625.595 1145.305,1625.595 ; J1.233@1144.835,1625.524 cw(c1145.006,1625.353) 1145.006,1625.595 ; J1.233@1144.835,1625.665 ccw(c1145.006,1625.836) 1145.006,1625.595
  TopLayer w0.4: J1.233@1143.715,1625.595 1145.205,1625.595 ; 1145.305,1625.595 1146,1624.9 1146,1623.4 1147.2,1622.2 1151.75,1622.2 1153.225,1620.725 1154.65,1619.3 1161.75,1619.3 1165.2,1622.75 R71.2@1170.6,1622.75 ; R71.2@1170.388,1622.538 ccw(c1169.876,1622.026) 1169.876,1622.75 ccw(c1169.876,1623.474) R71.2@1170.388,1622.962
VDEN: J1.75 R107.3 | length 49.5
  TopLayer w0.135: J1.75@1085.2,1636.8 1087.584,1636.8 1087.985,1636.399 1091.999,1636.399 ; J1.75@1086.344,1636.706 cw(c1086.57,1636.48) 1086.57,1636.8 cw(c1086.57,1637.12) J1.75@1086.344,1636.894
  TopLayer w0.2: 1092,1636.4 1097.33,1636.4 ; 1097.33,1636.395 1120.029,1613.697 1122.2,1613.697 1122.633,1613.264 R107.3@1122.633,1612 ; R107.3@1122.527,1612.456 ccw(c1122.271,1612.712) 1122.633,1612.712 ccw(c1122.995,1612.712) R107.3@1122.739,1612.456
VSYNC: J1.76 R107.2 | length 44.6
  TopLayer w0.2: J1.76@1090.398,1636.795 1097.496,1636.795 1120.194,1614.097 1122.503,1614.097 1123.522,1613.078 R107.2@1123.522,1612 ; R107.2@1123.416,1612.456 ccw(c1123.16,1612.712) 1123.522,1612.712 ccw(c1123.884,1612.712) R107.2@1123.628,1612.456
VSYNC_LDI: J1.83
WARM_RST: J1.137
WIFI_IO: RW18.1 WIFI2.15 | length 13.1
  TopLayer w0.2: RW18.1@1212.279,1645.805 1216.195,1645.805 1218.512,1643.488 WIFI2.15@1218.512,1642.088 ; RW18.1@1212.611,1645.522 cw(c1213.294,1644.839) 1213.294,1645.805 cw(c1213.294,1646.771) RW18.1@1212.611,1646.088 ; WIFI2.15@1218.158,1642.442 ccw(c1217.305,1643.295) 1218.512,1643.295 ccw(c1219.719,1643.295) WIFI2.15@1218.865,1642.442 ; WIFI2.15@1218.299,1642.3 ccw(c1217.787,1642.812) 1218.512,1642.812 ccw(c1219.236,1642.812) WIFI2.15@1218.724,1642.3
WIFI_PD: RW17.1 WIFI2.13 | length 20.7
  TopLayer w0.2: RW17.1@1208.579,1646.105 1209.174,1646.7 ; RW17.1@1208.654,1646.504 ccw(c1208.697,1647.176) 1209.174,1646.7 ; RW17.1@1209.02,1646.186 cw(c1209.572,1646.301) 1209.174,1646.7 ; WIFI2.13@1218.512,1640.088 1219.6,1641.176 1219.6,1643.7 1216.6,1646.7 1209.174,1646.7 ; WIFI2.13@1218.512,1640.388 ccw(c1218.512,1641.112) 1219.024,1640.6 ccw(c1219.536,1640.088) WIFI2.13@1218.812,1640.088 ; WIFI2.13@1218.512,1640.588 ccw(c1218.512,1641.795) 1219.365,1640.942 ccw(c1220.219,1640.088) WIFI2.13@1219.012,1640.088
WIFI_PWR: CW1.1 QW1.1 RW19.2 RW20.2 | length 14.1
  TopLayer w0.2: CW1.1@1201.605,1623.985 1203.192,1623.985 1203.271,1623.905 RW19.2@1203.271,1622.295 1204.919,1622.295 RW20.2@1204.929,1622.305 ; CW1.1@1201.888,1623.702 cw(c1202.571,1623.019) 1202.571,1623.985 cw(c1202.571,1624.95) CW1.1@1201.888,1624.267 ; 1202.448,1623.985 cw(c1202.448,1623.212) QW1.1@1202.994,1623.758 ; 1202.516,1623.985 ccw(c1202.516,1624.66) QW1.1@1202.994,1624.183 ; RW19.2@1202.989,1622.578 ccw(c1202.306,1623.261) 1203.271,1623.261 ccw(c1204.237,1623.261) RW19.2@1203.554,1622.578 ; QW1.1@1202.994,1623.558 cw(c1202.325,1622.889) 1203.271,1622.889 ; QW1.1@1203.136,1623.7 cw(c1202.807,1623.372) QW1.1@1203.271,1623.372 ; 1203.271,1623.204 cw(c1203.773,1623.204) QW1.1@1203.418,1623.558 ; RW19.2@1203.604,1622.012 cw(c1204.287,1621.329) 1204.287,1622.295 cw(c1204.287,1623.261) RW19.2@1203.604,1622.578 ; 1203.889,1622.295 ccw(c1203.889,1623.295) RW20.2@1204.596,1622.588 ; 1203.937,1622.295 cw(c1203.937,1621.363) RW20.2@1204.596,1622.022 ; 1204.372,1622.295 ccw(c1204.372,1622.812) RW20.2@1204.737,1622.446
XCLKOUT: J1.110
XEINT0: J1.1 J4.39 KEY1.1 R1.1 | length 144.5
  TopLayer w0.2: KEY1.1@1057.3,1579.6 1060.1,1582.4 ; KEY1.1@1057.566,1579.798 cw(c1057.681,1579.816) KEY1.1@1057.598,1579.898 ; KEY1.1@1057.763,1579.829 cw(c1058.161,1579.892) KEY1.1@1057.876,1580.176 ; KEY1.1@1057.961,1579.86 cw(c1058.641,1579.967) KEY1.1@1058.154,1580.454 ; KEY1.1@1058.158,1579.891 cw(c1059.122,1580.043) 1058.432,1580.732 ; KEY1.1@1058.356,1579.922 cw(c1059.602,1580.118) 1058.71,1581.01 ; KEY1.1@1058.554,1579.953 cw(c1060.083,1580.194) 1058.988,1581.288 ; KEY1.1@1058.751,1579.984 cw(c1060.563,1580.269) 1059.266,1581.566 ; KEY1.1@1058.949,1580.016 cw(c1061.043,1580.345) 1059.544,1581.844 ; KEY1.1@1059.146,1580.047 cw(c1061.524,1580.42) 1059.822,1582.122 ; KEY1.1@1059.344,1580.078 cw(c1062.004,1580.496) 1060.1,1582.4 ; R1.1@1061.717,1581.583 ccw(c1061.034,1582.266) 1062,1582.266 ccw(c1062.966,1582.266) R1.1@1062.283,1581.583 ; R1.1@1062,1581.3 1062,1582.4 ; 1083.883,1607.19 ccw(c1083.883,1607.467) J1.1@1084.079,1607.271 ; 1083.934,1607.19 cw(c1083.934,1606.984) J1.1@1084.079,1607.129 ; J1.1@1086.321,1607.129 cw(c1086.466,1606.984) 1086.466,1607.19 ; J1.1@1086.321,1607.271 ccw(c1086.517,1607.467) 1086.517,1607.19 ; v2(1087.5,1606.6) 1086.91,1607.19 1082.94,1607.19 1080.3,1604.55 1080.3,1587.963 1074.737,1582.4 1060.1,1582.4
  BottomLayer w0.2: v2(1087.5,1606.6) 1093.957,1606.6 1102.357,1615 1122.2,1615 1122.9,1615.7 1154.35,1615.7 1154.9,1616.25 J4.39@1156.5,1616.25 ; 1155.088,1616.25 ccw(c1155.088,1617.712) J4.39@1156.122,1616.678 ; 1155.329,1616.25 cw(c1155.329,1615.129) J4.39@1156.122,1615.922 ; 1155.571,1616.25 ccw(c1155.571,1617.229) J4.39@1156.263,1616.537 ; 1155.812,1616.25 cw(c1155.812,1615.612) J4.39@1156.263,1616.063
XEINT1: J1.2 J4.40 KEY2.1 R2.1 | length 142.9
  TopLayer w0.2: KEY2.1@1058.2,1571.9 1059.9,1571.9 ; KEY2.1@1059.083,1571.711 cw(c1059.48,1571.389) 1059.48,1571.9 cw(c1059.48,1572.411) KEY2.1@1059.083,1572.089 ; KEY2.1@1059.238,1571.585 cw(c1059.9,1571.048) 1059.9,1571.9 ; KEY2.1@1059.238,1572.215 ccw(c1059.9,1572.752) 1059.9,1571.9 ; 1059.982,1571.982 cw(c1060.75,1571.214) R2.1@1060.75,1572.3 ; 1060.103,1572.103 ccw(c1059.505,1572.7) R2.1@1060.35,1572.7 ; R2.1@1060.323,1572.323 cw(c1060.75,1571.896) R2.1@1060.75,1572.5 ; R2.1@1060.85,1573.1 ccw(c1060.85,1573.704) 1061.277,1573.277 ; R2.1@1061.05,1572.7 cw(c1061.895,1572.7) 1061.297,1573.297 ; R2.1@1061.25,1572.7 cw(c1062.578,1572.7) 1061.639,1573.639 ; 1089.073,1606.773 ccw(c1088.646,1607.2) J1.2@1089.25,1607.2 ; J1.2@1090.41,1607.19 1089.49,1607.19 v2(1088.2,1605.9) 1087.2,1605.9 1086.5,1606.6 1083.85,1606.6 1080.7,1603.45 1080.7,1587.797 1074.903,1582 1067.5,1582 1065.6,1580.1 1065.6,1577.6 1060.75,1572.75 1059.9,1571.9
  BottomLayer w0.2: v2(1088.2,1605.9) 1093.822,1605.9 1102.522,1614.6 1122.4,1614.6 1123.1,1615.3 1157.55,1615.3 J4.40@1158.5,1616.25 ; 1157.575,1615.325 ccw(c1156.633,1616.267) J4.40@1157.965,1616.291 ; 1157.672,1615.422 cw(c1158.5,1614.594) J4.40@1158.5,1615.765 ; 1157.908,1615.658 ccw(c1157.288,1616.279) J4.40@1158.165,1616.294 ; 1158.013,1615.763 cw(c1158.5,1615.277) J4.40@1158.5,1615.965
XEINT2: J1.3 J4.37 KEY3.1 R3.1 | length 142.4
  TopLayer w0.2: KEY3.1@1049.5,1575.9 1051.1,1575.9 ; KEY3.1@1050.562,1575.617 cw(c1051.1,1575.248) 1051.1,1575.9 ; KEY3.1@1050.562,1576.183 ccw(c1051.1,1576.552) 1051.1,1575.9 ; R3.1@1063.417,1583.717 cw(c1062.734,1583.034) 1063.7,1583.034 cw(c1064.666,1583.034) R3.1@1063.983,1583.717 ; 1063.7,1582.8 R3.1@1063.7,1584 ; 1083.883,1607.99 ccw(c1083.883,1608.267) J1.3@1084.079,1608.071 ; 1083.934,1607.99 cw(c1083.934,1607.784) J1.3@1084.079,1607.929 ; J1.3@1086.321,1607.929 cw(c1086.466,1607.784) 1086.466,1607.99 ; J1.3@1086.321,1608.071 ccw(c1086.517,1608.267) 1086.517,1607.99 ; v2@1087.49,1607.99 1082.99,1607.99 1079.9,1604.9 1079.9,1588.128 1074.572,1582.8 1058,1582.8 1051.1,1575.9
  BottomLayer w0.2: v2(1087.5,1608) 1094.225,1608 1102.025,1615.8 1121.6,1615.8 1122.4,1616.6 1153.45,1616.6 1155.1,1618.25 ; 1155.329,1618.25 cw(c1155.329,1617.129) J4.37@1156.122,1617.922 ; 1155.579,1618.25 ccw(c1155.579,1619.21) J4.37@1156.262,1618.535 ; 1155.812,1618.25 cw(c1155.812,1617.612) J4.37@1156.263,1618.063 ; J4.37@1156.119,1618.676 cw(c1155.1,1619.683) 1155.1,1618.25 ; J4.37@1156.5,1618.25 1155.1,1618.25
XEINT3: J1.4 J4.38 KEY4.1 R4.1 | length 140.1
  TopLayer w0.2: R4.1@1065.567,1572.983 ccw(c1064.522,1574.028) 1066,1574.028 ; R4.1@1065.709,1572.841 ccw(c1065.005,1573.545) 1066,1573.545 ; KEY4.1@1065.796,1575.546 cw(c1065.305,1575.055) 1066,1575.055 ; KEY4.1@1065.796,1576.254 ccw(c1065.305,1576.745) 1066,1576.745 ; R4.1@1066,1572.7 1066,1579.934 1067.666,1581.6 1075.069,1581.6 1081.1,1587.631 1081.1,1602.75 1084.25,1605.9 v2(1086.2,1605.9) ; 1066,1573.304 ccw(c1066.454,1573.304) R4.1@1066.133,1572.983 ; 1066,1574.331 cw(c1067.719,1574.331) KEY4.1@1066.504,1575.546 ; 1066,1574.814 cw(c1067.236,1574.814) KEY4.1@1066.362,1575.688 ; 1066,1575.296 cw(c1066.754,1575.296) KEY4.1@1066.221,1575.829 ; 1066,1576.504 ccw(c1066.754,1576.504) KEY4.1@1066.221,1575.971 ; 1066,1576.986 ccw(c1067.236,1576.986) KEY4.1@1066.362,1576.112 ; 1066,1577.469 ccw(c1067.719,1577.469) KEY4.1@1066.504,1576.254 ; v2(1088.2,1607.3) 1088.89,1607.99 J1.4@1090.41,1607.99 ; 1089.083,1607.99 ccw(c1089.083,1608.267) J1.4@1089.279,1608.071 ; 1089.134,1607.99 cw(c1089.134,1607.784) J1.4@1089.279,1607.929
  BottomLayer w0.2: v2(1086.2,1605.9) 1086.2,1606.6 1086.9,1607.3 1094.091,1607.3 1102.191,1615.4 1121.9,1615.4 1122.6,1616.1 1153.9,1616.1 1155.1,1617.3 1157.55,1617.3 ; 1157.565,1617.315 J4.38@1158.5,1618.25 ; 1157.59,1617.34 ccw(c1156.683,1618.247) J4.38@1157.965,1618.284 ; 1157.672,1617.422 cw(c1158.5,1616.594) J4.38@1158.5,1617.765 ; 1157.918,1617.668 ccw(c1157.32,1618.266) J4.38@1158.165,1618.29 ; 1158.013,1617.763 cw(c1158.5,1617.277) J4.38@1158.5,1617.965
